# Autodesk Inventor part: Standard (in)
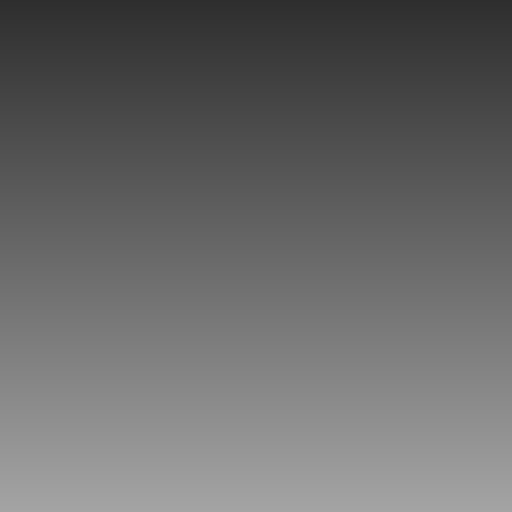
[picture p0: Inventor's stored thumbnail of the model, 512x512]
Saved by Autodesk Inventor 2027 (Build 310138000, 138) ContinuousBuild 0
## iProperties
Shininess: 64.0
Length Units: 11272
Angle Units: 11279
Time Units: 11290
Mass Units: 11286
Length Display Precision: 3
Angle Display Precision: 2
Compacted: True
Part Number: Standard (in)
Document SubType Name: Modeling
Created: 2002-08
Density: 1 g/cm^3
Material: Generic
Appearance: Default
Density: 0.0
Volumn: 0.0
Area: 0.0
PropertySet Name: Model Information
Control State: 0
Master: False
Checked Out: False
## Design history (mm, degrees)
